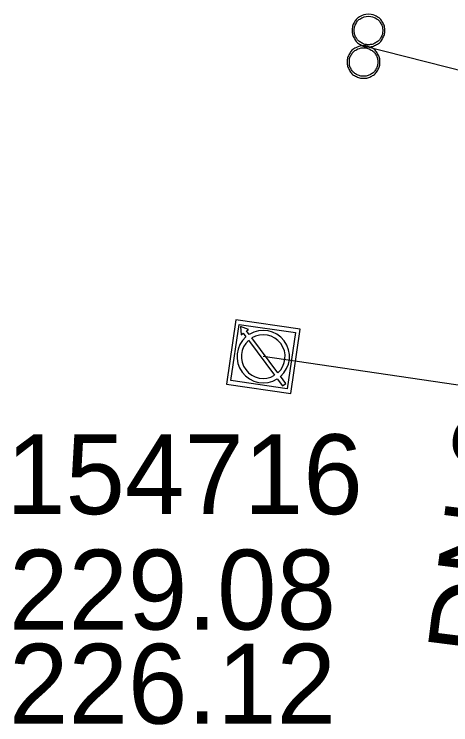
# Model space of a CAD drawing. Extents: x -595129 to -593591, y -1168385 to -1166898.
# Drawn here: x -594638.13 to -594630.48, y -1167147.5 to -1167135.05 of the extents above; entities that cross this region are included whole.
import ezdxf

# ---------------------------------------------------------------- set-up
doc = ezdxf.new("R2010")
doc.units = 0
for name, color, linetype in [('DA Kanalizační stoka popis', 7, 'Continuous'), ('Default', 7, 'Continuous'), ('Identifikace', 7, 'Continuous'), ('Kanalizační přípojka', 7, 'Continuous'), ('Popis šachty', 7, 'Continuous'), ('V Odběrné místo', 7, 'Continuous'), ('V Přípojka', 7, 'Continuous')]:
    doc.layers.add(name, color=color, linetype=linetype)

msp = doc.modelspace()

# ---------------------------------------------------------------- linework, layer by layer
at = {"layer": 'Default'}
for points in [[(-594631.926, -1167135.048), (-594631.854, -1167135.048), (-594631.786, -1167135.085), (-594631.718, -1167135.121), (-594631.68, -1167135.19), (-594631.641, -1167135.259), (-594631.641, -1167135.333), (-594631.641, -1167135.407), (-594631.679, -1167135.475), (-594631.716, -1167135.543), (-594631.784, -1167135.58), (-594631.852, -1167135.618), (-594631.926, -1167135.618), (-594632, -1167135.618), (-594632.068, -1167135.58), (-594632.136, -1167135.543), (-594632.173, -1167135.475), (-594632.211, -1167135.407), (-594632.211, -1167135.333), (-594632.211, -1167135.259), (-594632.173, -1167135.19), (-594632.134, -1167135.121), (-594632.066, -1167135.085), (-594631.998, -1167135.048), (-594631.926, -1167135.048)], [(-594631.926, -1167135.084), (-594631.989, -1167135.084), (-594632.049, -1167135.116), (-594632.109, -1167135.148), (-594632.142, -1167135.208), (-594632.175, -1167135.268), (-594632.175, -1167135.333), (-594632.175, -1167135.398), (-594632.143, -1167135.457), (-594632.11, -1167135.516), (-594632.05, -1167135.549), (-594631.991, -1167135.582), (-594631.926, -1167135.582), (-594631.861, -1167135.582), (-594631.802, -1167135.549), (-594631.742, -1167135.516), (-594631.709, -1167135.457), (-594631.677, -1167135.398), (-594631.677, -1167135.333), (-594631.677, -1167135.268), (-594631.71, -1167135.208), (-594631.744, -1167135.148), (-594631.804, -1167135.116), (-594631.863, -1167135.084), (-594631.926, -1167135.084)], [(-594632.012, -1167135.601), (-594631.94, -1167135.601), (-594631.872, -1167135.638), (-594631.804, -1167135.674), (-594631.766, -1167135.743), (-594631.727, -1167135.812), (-594631.727, -1167135.886), (-594631.727, -1167135.96), (-594631.765, -1167136.028), (-594631.802, -1167136.096), (-594631.87, -1167136.133), (-594631.938, -1167136.171), (-594632.012, -1167136.171), (-594632.086, -1167136.171), (-594632.154, -1167136.133), (-594632.222, -1167136.096), (-594632.259, -1167136.028), (-594632.297, -1167135.96), (-594632.297, -1167135.886), (-594632.297, -1167135.812), (-594632.259, -1167135.743), (-594632.22, -1167135.674), (-594632.152, -1167135.638), (-594632.084, -1167135.601), (-594632.012, -1167135.601)], [(-594632.012, -1167135.637), (-594632.075, -1167135.637), (-594632.135, -1167135.669), (-594632.195, -1167135.701), (-594632.228, -1167135.761), (-594632.261, -1167135.821), (-594632.261, -1167135.886), (-594632.261, -1167135.951), (-594632.229, -1167136.01), (-594632.196, -1167136.069), (-594632.136, -1167136.102), (-594632.077, -1167136.135), (-594632.012, -1167136.135), (-594631.947, -1167136.135), (-594631.888, -1167136.102), (-594631.828, -1167136.069), (-594631.795, -1167136.01), (-594631.763, -1167135.951), (-594631.763, -1167135.886), (-594631.763, -1167135.821), (-594631.796, -1167135.761), (-594631.83, -1167135.701), (-594631.89, -1167135.669), (-594631.949, -1167135.637), (-594632.012, -1167135.637)]]:
    msp.add_open_spline(points, degree=3, dxfattribs=at)
at = {"layer": 'Kanalizační přípojka'}
msp.add_lwpolyline([(-594632.006, -1167135.602), (-594627.663, -1167136.707)], dxfattribs=at)
at = {"layer": 'V Odběrné místo'}
for p, q in [((-594634.026, -1167140.765), (-594633.57, -1167141.378)), ((-594633.513, -1167141.335), (-594633.968, -1167140.722))]:
    msp.add_line(p, q, dxfattribs=at)
for points in [[(-594633.287, -1167141.696), (-594633.123, -1167140.568), (-594634.251, -1167140.404), (-594634.415, -1167141.532)], [(-594633.347, -1167141.615), (-594634.334, -1167141.472), (-594634.191, -1167140.485), (-594633.204, -1167140.628)]]:
    msp.add_lwpolyline(points, close=True, dxfattribs=at)
for points in [[(-594634.015, -1167140.661), (-594634.061, -1167140.599), (-594634.028, -1167140.575), (-594634.167, -1167140.52), (-594634.155, -1167140.67), (-594634.118, -1167140.642), (-594634.072, -1167140.704)], [(-594633.524, -1167141.439), (-594633.43, -1167141.564), (-594633.373, -1167141.522), (-594633.466, -1167141.396)]]:
    msp.add_lwpolyline(points, dxfattribs=at)
for radius, start, end in [(0.46, 311.1261, 122.2813), (0.46, 131.1768, 302.231), (0.383, 132.0675, 301.3403), (0.383, 312.0168, 121.3373)]:
    msp.add_arc((-594633.769, -1167141.05), radius, start, end, dxfattribs=at)
at = {"layer": 'V Přípojka'}
msp.add_lwpolyline([(-594629.36, -1167141.695), (-594629.604, -1167141.66), (-594633.769, -1167141.051)], dxfattribs=at)

# ---------------------------------------------------------------- texts
at = {"layer": 'DA Kanalizační stoka popis'}
msp.add_text('DN 300 BEO', height=1.4, rotation=82.7924, dxfattribs=at).set_placement((-594629.508, -1167146.378))
at = {"layer": 'Identifikace'}
msp.add_text('154716', height=1.4, dxfattribs=at).set_placement((-594638.273, -1167143.812))
at = {"layer": 'Popis šachty'}
for s, p in [('229.08', (-594638.221, -1167145.835)), ('226.12', (-594638.221, -1167147.485))]:
    msp.add_text(s, height=1.4, dxfattribs=at).set_placement(p)

doc.saveas('drawing.dxf')
